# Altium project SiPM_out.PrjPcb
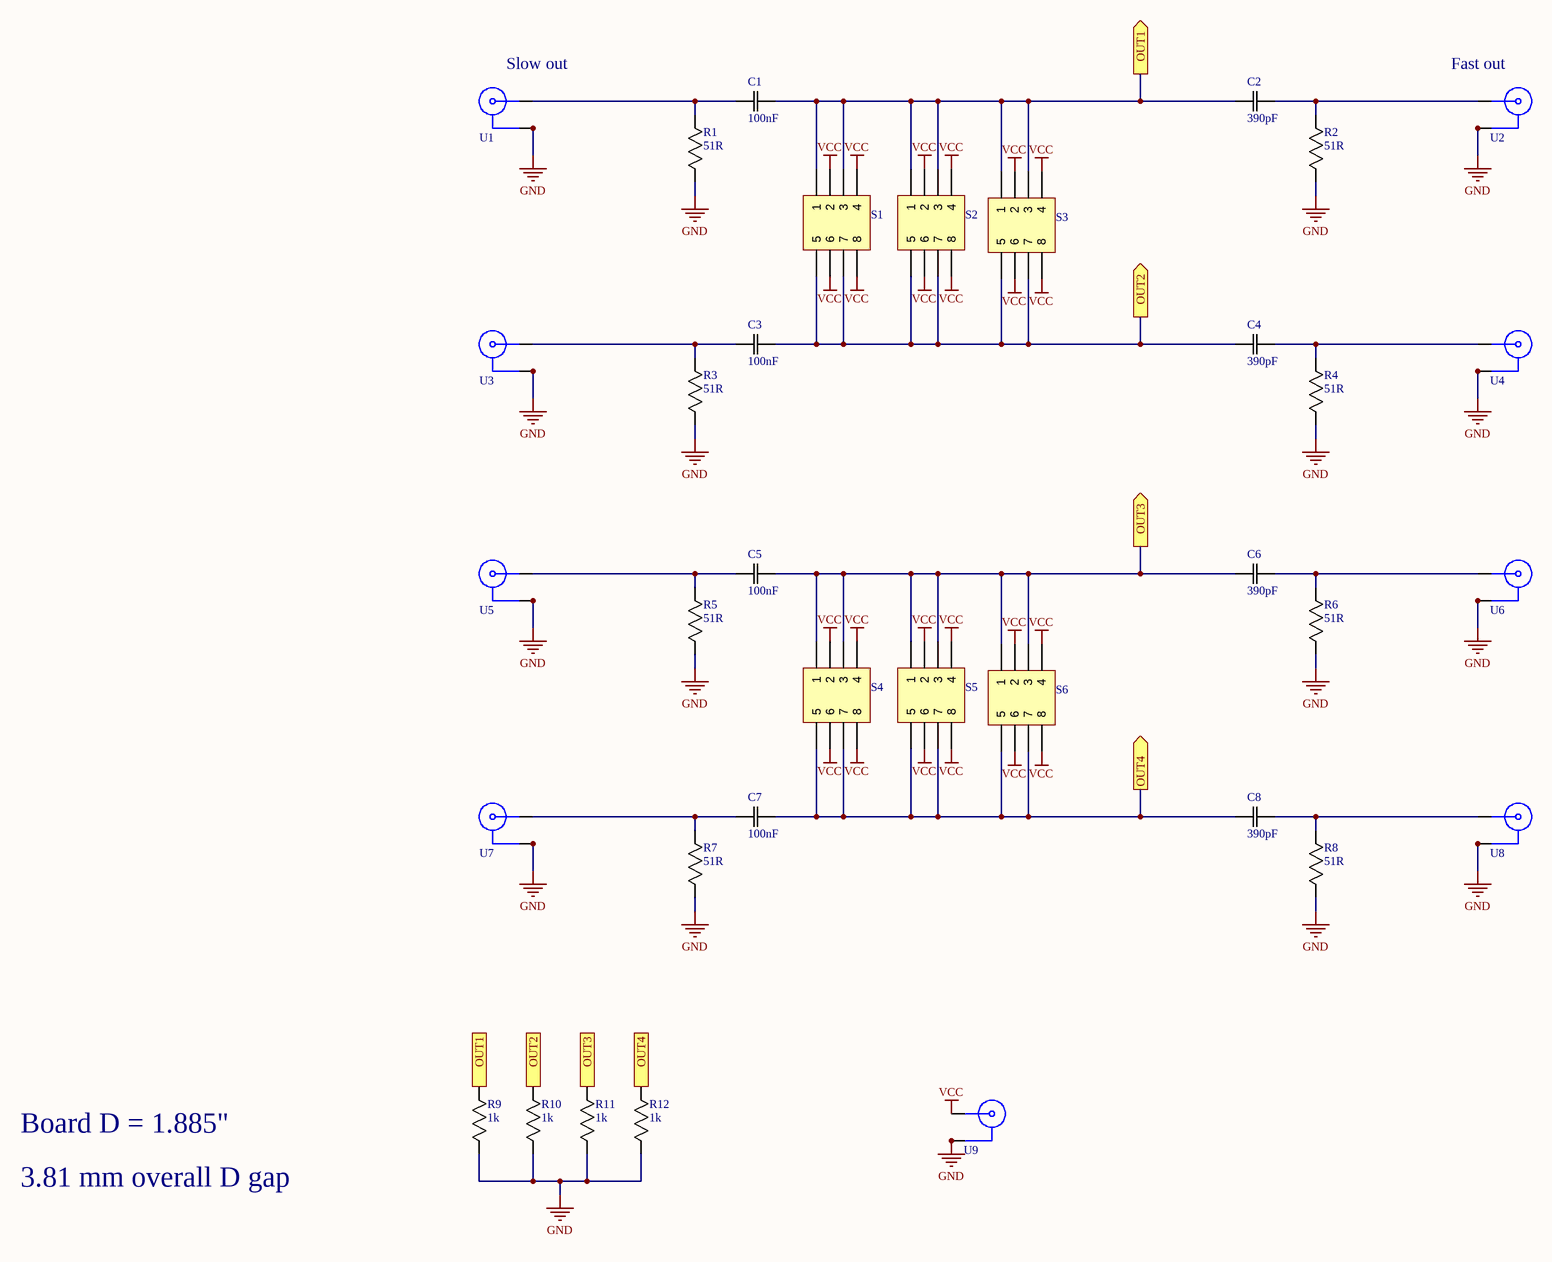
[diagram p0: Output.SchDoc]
2 sheets, 43 parts. Net scope: flat (ports and power ports of the same name join across sheets).
Board file: SIPM_out.PcbDoc
Sheets:
  Output.SchDoc
  Power.SchDoc

## Sheet Output.SchDoc
size 431 x 279 mm; SheetNumber: 1; SheetTotal: 2

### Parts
C1  100nF  [0805]
C2  390pF  [0805]
C3  100nF  [0805]
C4  390pF  [0805]
C5  100nF  [0805]
C6  390pF  [0805]
C7  100nF  [0805]
C8  390pF  [0805]
R1  51R  [0805]
R2  51R  [0805]
R3  51R  [0805]
R4  51R  [0805]
R5  51R  [0805]
R6  51R  [0805]
R7  51R  [0805]
R8  51R  [0805]
R9  1k  [0805]
R10  1k  [0805]
R11  1k  [0805]
R12  1k  [0805]
S1  110-87-308-41-001101  [DIP 2x4]  (value not drawn)
S2  110-87-308-41-001101  [DIP 2x4]  (value not drawn)
S3  110-87-308-41-001101  [DIP 2x4]  (value not drawn)
S4  110-87-308-41-001101  [DIP 2x4]  (value not drawn)
S5  110-87-308-41-001101  [DIP 2x4]  (value not drawn)
S6  110-87-308-41-001101  [DIP 2x4]  (value not drawn)
U1  MMCX Jack  [MMCX]  (value not drawn)
U2  MMCX Jack  [MMCX]  (value not drawn)
U3  MMCX Jack  [MMCX]  (value not drawn)
U4  MMCX Jack  [MMCX]  (value not drawn)
U5  MMCX Jack  [MMCX]  (value not drawn)
U6  MMCX Jack  [MMCX]  (value not drawn)
U7  MMCX Jack  [MMCX]  (value not drawn)
U8  MMCX Jack  [MMCX]  (value not drawn)
U9  MMCX Jack  [MMCX]  (value not drawn)

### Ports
OUT1 (in), OUT1 (out), OUT2 (in), OUT2 (out), OUT3 (in), OUT3 (out), OUT4 (in), OUT4 (out)

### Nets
GND: R1.1 R2.1 R3.1 R4.1 R5.1 R6.1 R7.1 R8.1 R9.1 R10.1 R11.1 R12.1 U1.2 U1.2,3,4 U2.2 U2.2,3,4,5 U3.2 U3.2,3,4 U4.2 U4.2,3,4,5 U5.2 U5.2,3,4,5 U6.2 U6.2,3,4,5 U7.2 U7.2,3,4,5 U8.2 U8.2,3,4,5 U9.2 U9.2,3,4
VCC: S1.2 S1.4 S1.6 S1.8 S2.2 S2.4 S2.6 S2.8 S3.2 S3.4 S3.6 S3.8 S4.2 S4.4 S4.6 S4.8 S5.2 S5.4 S5.6 S5.8 S6.2 S6.4 S6.6 S6.8 U9.1
NetC1_1: C1.1 R1.2 U1.1
NetC1_2: C1.2 C2.1 R9.2 S1.1 S1.3 S2.1 S2.3 S3.1 S3.3 ; port OUT1
NetC2_2: C2.2 R2.2 U2.1
NetC3_1: C3.1 R3.2 U3.1
NetC3_2: C3.2 C4.1 R10.2 S1.5 S1.7 S2.5 S2.7 S3.5 S3.7 ; port OUT2
NetC4_2: C4.2 R4.2 U4.1
NetC5_1: C5.1 R5.2 U5.1
NetC5_2: C5.2 C6.1 R11.2 S4.1 S4.3 S5.1 S5.3 S6.1 S6.3 ; port OUT3
NetC6_2: C6.2 R6.2 U6.1
NetC7_1: C7.1 R7.2 U7.1
NetC7_2: C7.2 C8.1 R12.2 S4.5 S4.7 S5.5 S5.7 S6.5 S6.7 ; port OUT4
NetC8_2: C8.2 R8.2 U8.1

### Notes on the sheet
- (near U1) Slow out
- (near U2) Fast out
- Board D = 1.885"
- 3.81 mm overall D gap

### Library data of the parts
C1 C3 C5 C7 = CAP 100n 5% 0805: CAP CER 0.1UF 50V X7R 0805; Manufacturer: Kyocera AVX; Manufacturer Part Number: 08055C104JAT2A; Dielectric Material: Ceramic; Tolerance: 5%; Dissipation Factor: 2.5%; Insulation Resistance: 100GR
C2 C4 C6 C8 = CAP 390pF 5% 0805: CAP CER 390PF 50V C0G/NP0 0805; Manufacturer: Kyocera AVX; Manufacturer Part Number: 08055A391JAT2A; Dielectric Material: Ceramic; Tolerance: 5%; Dielectric: C0G; Temperature Coefficient: 30ppm/°C
R1-R8 = RES 51R 5% 0805: RES SMD 51 OHM 5% 1/2W 0805; Manufacturer: Panasonic; Manufacturer Part Number: ERJ-P06J510V; Temperature Coefficient: 200ppm/°C; Power Rating: 500mW; Voltage Rating: 150V
R9-R12 = RES 1k 0.1% 0805: RES SMD 1K OHM 0.1% 1W 0805; Manufacturer: Vishay Dale Thin Film; Manufacturer Part Number: PCAN0805E1001BST5; Resistance: 1kR; Temperature Coefficient: 25ppm/°C
S1-S6 = Socket 2x4: CONN IC DIP SOCKET 8POS GOLD; Manufacturer: Preci-Dip; Current Rating: 1A; Contact Resistance: 10mR; Number of Contacts: 8; Voltage Rating: 150V; Voltage Rating (AC): 100V; Insulation Resistance: 10GR; Gender: Female; Pitch: 2.54mm; Row Spacing: 7.62mm
U1-U9 = MMCX Jack: CONN MMCX PLUG STR 50 OHM PCB; Manufacturer: Samtec; Manufacturer Part Number: MMCX-P-P-H-ST-TH1; Body Plating: Gold; Body Material: Brass; Frequency: 6Hz; Impedance: 50R; Operating Frequency: 0 to 6Hz; Connector Type: MMCX,Coaxial; Max Frequency: 6GHz

## Sheet Power.SchDoc
size A4; SheetNumber: 2; SheetTotal: 2
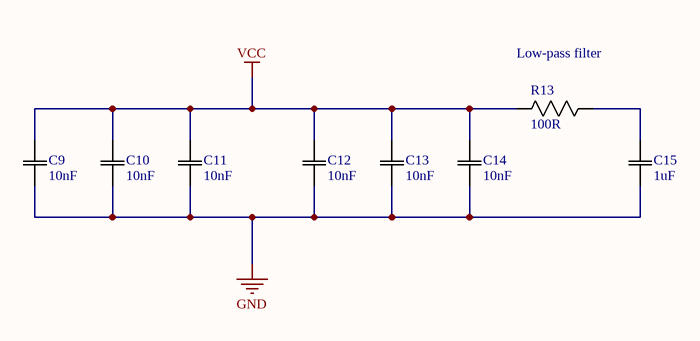
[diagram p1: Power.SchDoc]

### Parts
C9  10nF  [0805]
C10  10nF  [0805]
C11  10nF  [0805]
C12  10nF  [0805]
C13  10nF  [0805]
C14  10nF  [0805]
C15  1uF  [0805]
R13  100R  [0805]

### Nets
GND: C9.1 C10.1 C11.1 C12.1 C13.1 C14.1 C15.1
VCC: C9.2 C10.2 C11.2 C12.2 C13.2 C14.2 R13.1
NetC15_2: C15.2 R13.2

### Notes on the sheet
- (near R13) Low-pass filter

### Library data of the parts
C9-C14 = CAP 10n 10% 0805: CAP CER 10000PF 50V X7R 0805; Manufacturer: Kyocera AVX; Manufacturer Part Number: 08055C103KAT2A; Dielectric Material: Ceramic; Tolerance: 10%; Insulation Resistance: 100GR; Dissipation Factor: 2.5%
C15 = CAP 1u 10% 0805: CAP CER 1UF 50V X7R 0805; Manufacturer: Kyocera AVX; Manufacturer Part Number: 08055C105KAT2A; Tolerance: 10%; Dissipation Factor: 2.5%
R13 = RES 100R 1% 0805: RES SMD 100 OHM 1% 1/2W 0805; Manufacturer: Panasonic; Manufacturer Part Number: ERJ-P06F1000V; Temperature Coefficient: 100ppm/°C; Power Rating: 500mW; Voltage Rating: 150V

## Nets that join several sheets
GND: Output (30 pins), Power (7 pins)
VCC: Output (25 pins), Power (7 pins)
